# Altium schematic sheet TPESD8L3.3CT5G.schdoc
size 127 x 101 mm
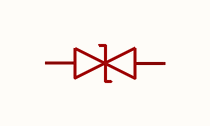
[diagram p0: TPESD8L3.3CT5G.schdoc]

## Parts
D?  tpesd8l3.3ct5g  [DFN1006-2L-BI-1]  (value not drawn)

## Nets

Not connected (* = marked no-connect by the designer): D? 1 2

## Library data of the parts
D? = tpesd8l3.3ct5g: 极性:双向;反向截止电压(Vrwm):3.3V;钳位电压:8V;峰值脉冲电流(Ipp):4A@8/20us;峰值脉冲功率(Ppp):70W@8/20us;击穿电压(VBR):5V;; Manufacturer: TECH PUBLIC(台舟); AddInBom: yes; ModelId: 4f73e746f3be4d299816d29f03249d6e; ModelTransform: 40.1574,24.4094,0,0,0,0,0,0,0; Polarity: 双向; Reverse Stand-Off Voltage (Vrwm): 3.3V; Clamping Voltage: 8V; Voltage - Breakdown: 5V; Reverse Leakage Current (Ir): 80nA; Number of Channels: 单路; level of protection: IEC 61000-4-5；IEC 61000-4-2; Type: ESD; Junction Capacitance: 0.3pF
